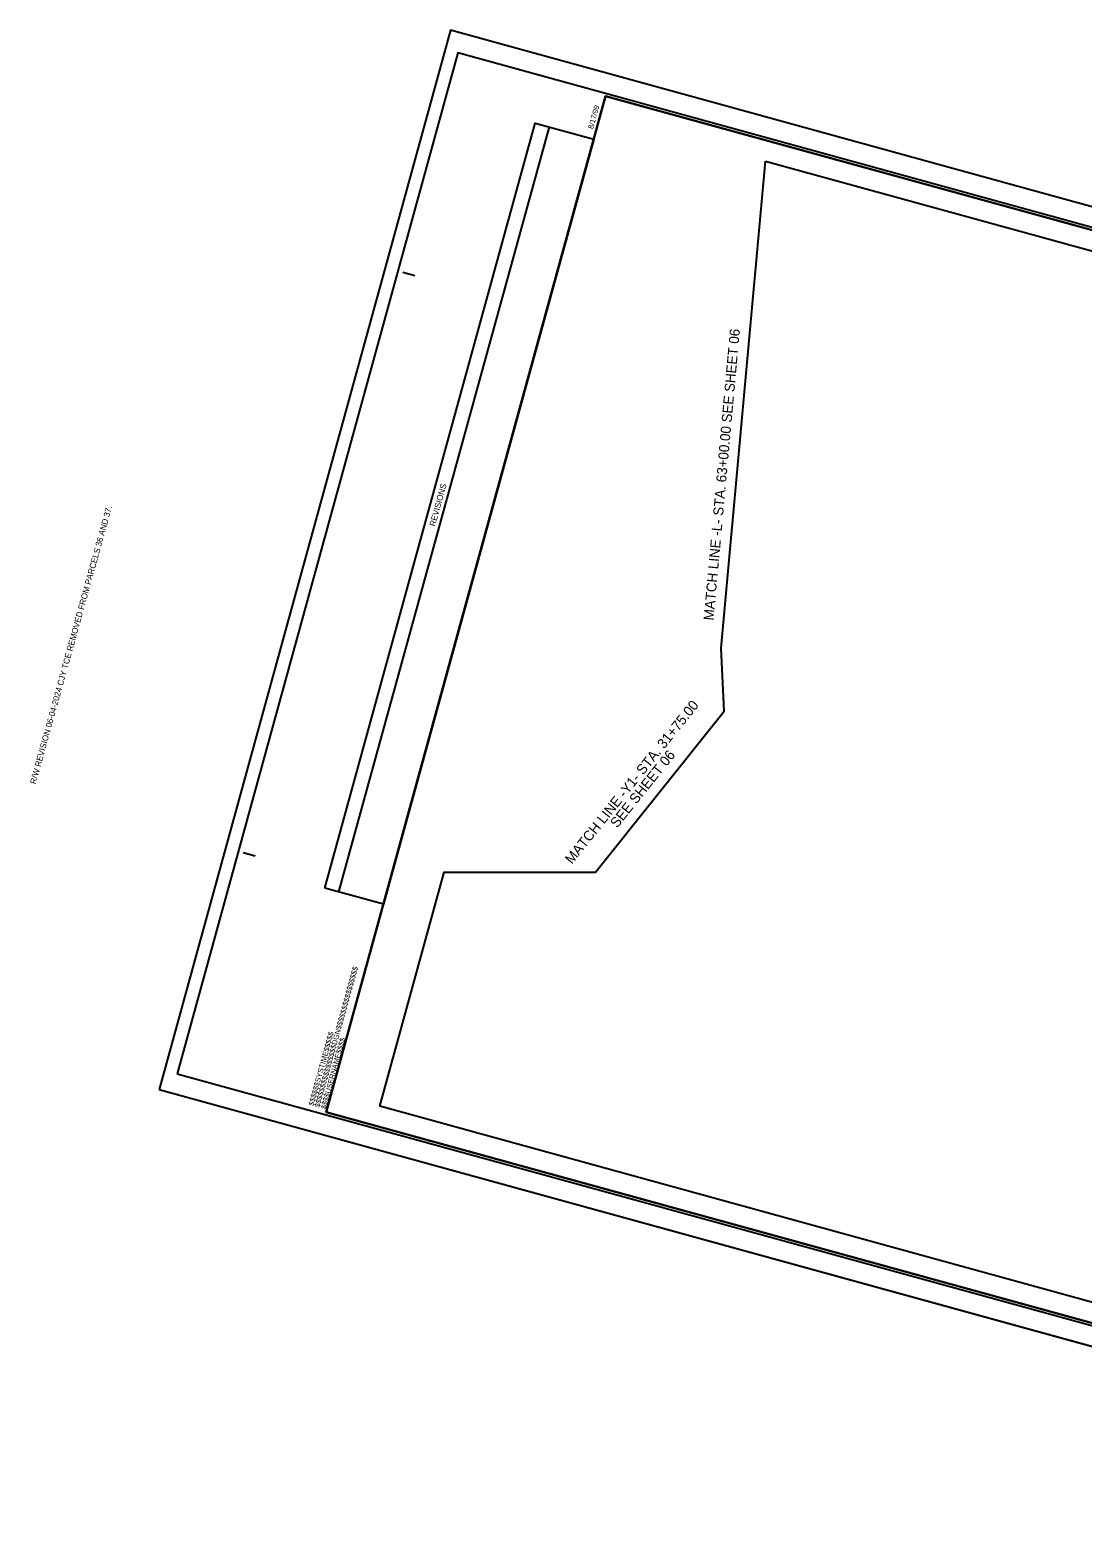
# Model space of a CAD drawing. Extents: x 1641063 to 2864602, y 841295 to 973236.
# Drawn here: x 1641063 to 1642113, y 841295 to 842798 of the extents above; entities that cross this region are included whole.
import ezdxf

# ---------------------------------------------------------------- set-up
doc = ezdxf.new("R2010")
doc.units = 0
for name, color, linetype in [('Old_Level_4', 7, 'Continuous'), ('Prop CMT Conc Surface', 7, 'Continuous'), ('Prop CMT Concrete Structures', 7, 'Continuous'), ('Prop CMT DNC', 7, 'Continuous'), ('Prop Dimension', 7, 'Continuous'), ('Prop Dimension Text', 7, 'Continuous'), ('Prop PHM Wetland Impact Area Boundary Line', 7, 'Continuous'), ('Prop Superelevation Label', 7, 'Continuous')]:
    doc.layers.add(name, color=color, linetype=linetype)

msp = doc.modelspace()

# ---------------------------------------------------------------- linework, layer by layer
at = {"layer": 'Old_Level_4'}
msp.add_lwpolyline([(1641192.1, 841742), (1642815.3, 841295.3), (1643105.8, 842351.1), (1641482.6, 842797.7)], close=True, dxfattribs=at)
msp.add_lwpolyline([(1641192.1, 841742), (1642815.3, 841295.3), (1643105.8, 842351.1), (1641482.6, 842797.7)], close=True, dxfattribs=at)
at = {"layer": 'Prop CMT Concrete Structures'}
for p, q in [((1641637.2, 842731.9), (1641637.2, 842731.9)), ((1641435, 842556.7), (1641447, 842553.4)), ((1641275.8, 841978.2), (1641287.9, 841974.9)), ((1641358.6, 841719.5), (1641358.6, 841719.5))]:
    msp.add_line(p, q, dxfattribs=at)
for points in [[(1643083.5, 842333.9), (1641637.2, 842731.9), (1641358.6, 841719.5), (1642804.8, 841321.5)], [(1641358.6, 841719.5), (1641637.2, 842731.9), (1642890.6, 842387), (1642850.8, 842242.3), (1643043.6, 842189.2), (1642804.8, 841321.5)]]:
    msp.add_lwpolyline(points, close=True, dxfattribs=at)
at = {"layer": 'Prop CMT DNC'}
msp.add_line((1641627.1, 841958.8), (1641755.5, 842119.2), dxfattribs=at)
msp.add_lwpolyline([(1641476.3, 841958.8), (1641627.1, 841958.8), (1641755.5, 842119.2), (1641752.4, 842181.8), (1641796.6, 842667.3)], dxfattribs=at)
at = {"layer": 'Prop Dimension'}
msp.add_line((1641371.3, 841939), (1641581.1, 842701.3), dxfattribs=at)
msp.add_lwpolyline([(1641357.3, 841942.8), (1641567.1, 842705.2), (1641625.4, 842689.1), (1641415.7, 841926.8)], close=True, dxfattribs=at)
at = {"layer": 'Prop Dimension Text'}
msp.add_lwpolyline([(1641209.9, 841757.8), (1642816.2, 841315.8), (1643096.2, 842333), (1641489.9, 842775)], close=True, dxfattribs=at)
at = {"layer": 'Prop PHM Wetland Impact Area Boundary Line'}
msp.add_line((1641796.6, 842667.3), (1642584.6, 842450.4), dxfattribs=at)
msp.add_lwpolyline([(1642834.8, 842332.3), (1642796.6, 842193.5), (1642979.1, 842143.2), (1642931.9, 841980.8), (1642684.7, 842016.9), (1642616.5, 841780.2), (1642867.9, 841712.2), (1642769.9, 841383), (1642620.7, 841424), (1642612.8, 841395.1), (1641412.1, 841725.5), (1641476.3, 841958.8), (1641627.1, 841958.8), (1641755.5, 842119.2), (1641752.4, 842181.8), (1641796.6, 842667.3)], dxfattribs=at)
at = {"layer": 'Prop Superelevation Label'}
for p, q in [((1641482.6, 842797.7), (1641192.1, 841742)), ((1641192.1, 841742), (1642815.3, 841295.3))]:
    msp.add_line(p, q, dxfattribs=at)

# ---------------------------------------------------------------- texts
at = {"layer": 'Prop CMT Conc Surface'}
for s, rotation, p in [('MATCH LINE -L- STA. 63+00.00 SEE SHEET 06', 84.8005, (1641744.8, 842209.2)), ('MATCH LINE -Y1- STA. 31+75.00', 51.3193, (1641603.6, 841966.1)), ('SEE SHEET 06', 51.3193, (1641648.7, 842002.1))]:
    msp.add_text(s, height=10, rotation=rotation, dxfattribs=at).set_placement(p)
at = {"layer": 'Prop CMT Concrete Structures'}
for s, p in [('8/17/99', (1641624.7, 842698.8)), ('$$$$$$$$$$$$$$$$DGN$$$$$$$$$$$$$$$$', (1641351.9, 841723.8)), ('$$$$$$SYSTIME$$$$$', (1641346, 841725.4)), ('$$$$USERNAME$$$$', (1641358.2, 841722.1))]:
    msp.add_text(s, height=5.25, rotation=74.6135, dxfattribs=at).set_placement(p)
at = {"layer": 'Prop Dimension'}
for s, p in [('REVISIONS', (1641467.2, 842302.8)), ('R/W REVISION 06-04-2024 CJY TCE REMOVED FROM PARCELS 36 AND 37.', (1641069, 842046))]:
    msp.add_text(s, height=6, rotation=74.6135, dxfattribs=at).set_placement(p)

doc.saveas('drawing.dxf')
